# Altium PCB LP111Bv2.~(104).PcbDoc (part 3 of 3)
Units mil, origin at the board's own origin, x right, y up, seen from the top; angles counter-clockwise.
Board outline 3543.31 x 7480.32 mil, 4 copper layers (Top Layer, Signal Layer 1, Signal Layer 2, Bottom Layer), stack 40 mil thick; 284 components, 118 nets, 594 pads, 103 vias.
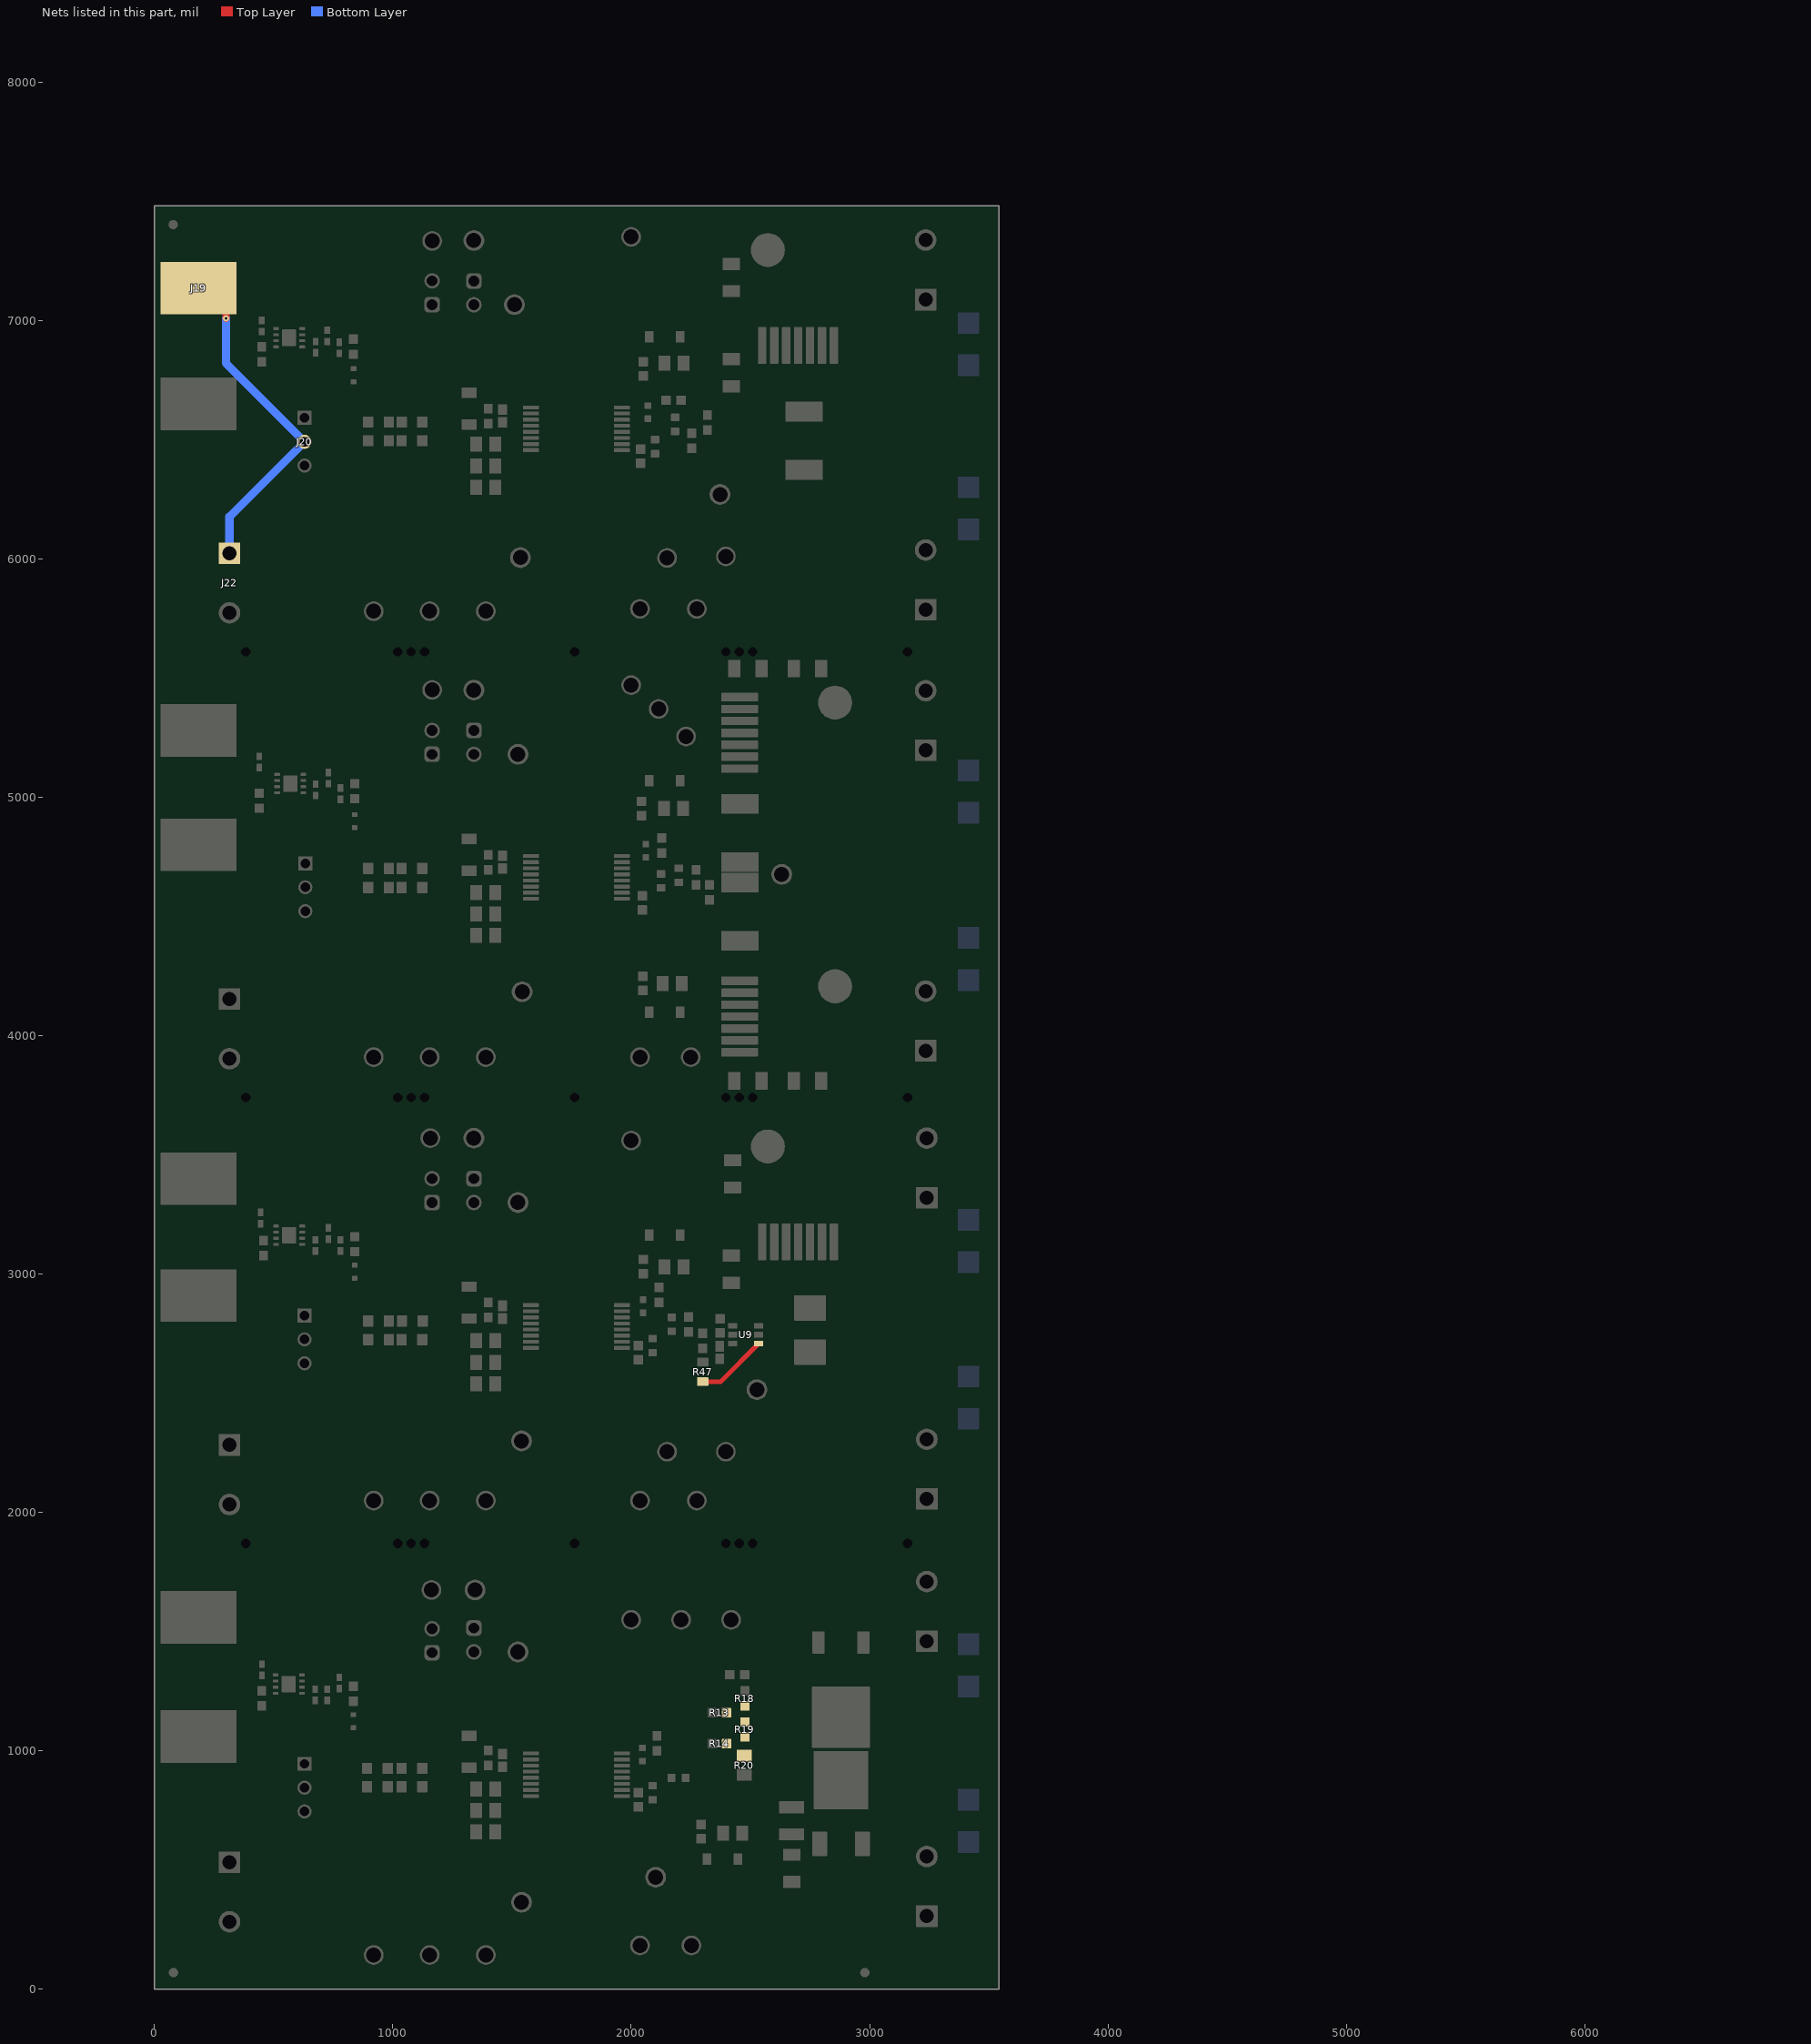
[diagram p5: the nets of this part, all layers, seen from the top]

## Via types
v1: diameter 24, hole 8, Top Layer to Bottom Layer, tented both sides, 77 vias
v2: diameter 19.68, hole 7.87, Top Layer to Bottom Layer, 16 vias
v3: diameter 27.56, hole 11.81, Top Layer to Bottom Layer, tented both sides, 10 vias

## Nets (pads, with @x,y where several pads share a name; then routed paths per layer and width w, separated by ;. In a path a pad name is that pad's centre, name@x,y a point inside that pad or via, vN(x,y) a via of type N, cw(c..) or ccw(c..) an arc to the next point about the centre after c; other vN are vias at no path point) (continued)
NetJ19_1: J19.1 J20.2 J22.1 | length 1436.1
  Top Layer w20: J19.1@185,7135.83 200,7135.83 J19.1@300,7035.83
  Top Layer w30: v3(300,7008.02) J19.1@300,7035.83
  Bottom Layer w35: v3(300,7008.02) 300,6820.86 J20.2@629.87,6490.99 314.96,6176.08 J22.1@314.96,6023.19
NetR13_2: R13.2 R18.1 R19.2
NetR14_2: R14.2 R19.1 R20.2
NetR47_2: R47.2 U9.1 | length 300.2
  Top Layer w20: R47.2@2299.93,2548.66 2374.8,2548.66 U9.1@2534.13,2707.99
pads on no net: FID1.1 FID2.1 FID3.1 H1.0 H2.0 H3.0 H4.0 H5.0 H6.0 H7.0 H8.0 H9.0 H10.0 H11.0 H12.0 H13.0 H14.0 H15.0 H16.0 SH-J1.0 SH-J2.0 SH-J3.0 SH-J4.0 SH-J5.0 SH-J6.0 SH-J7.0 SH-J8.0 SH-J9.0 SH-J10.0 SH-J11.0 SH-J12.0 U2.3 U2.7 U3.3 U3.7 U5.3 U5.7 U8.3 U8.7

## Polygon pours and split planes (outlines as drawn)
2VSSS on Top Layer "TOP_LAYER_2VSSS_P056" (solid, remove dead copper, pour order 56): 1930.14,4522.73 1930.14,4806.94 1982.34,4859.14 2249.94,4859.14 2291.63,4817.45 2291.63,4511.77 2250.63,4470.77 1982.1,4470.77
4VSSS on Top Layer "Top Layer-4VSSS" (solid, remove dead copper, pour order 52): 1930,115 2025,20 3062,20 3543.31,20 3543.31,475 3530,475 3530,662.5 2940,662.5 2940,565.32 2849.68,475 2247.51,475 2177.76,544.75 2177.76,691.48 2231,744.72 2369.48,744.72 2505.62,880.87 2504.34,882.14 2504.34,927.5 2275.27,1156.58 2000,1156.58 1928.23,1084.81 1928.23,744.72 1930,744.72
2VSSP on Top Layer "TOP_LAYER_2VSSP_P019" (solid, remove dead copper, pour order 19): 419.5,4935.31 548.27,4935.31 636.75,5023.78 860.61,5023.78 868.48,5031.65 868.48,5120.51 800.49,5188.5 419.5,5188.5
4VSSP on Top Layer "TOP_LAYER_4VSSP_P025" (solid, remove dead copper, pour order 25): 429.46,1160.97 543.34,1160.97 631.81,1249.45 855.67,1249.45 863.54,1257.32 863.54,1346.18 830.42,1379.31 429.46,1379.31
3VSSP on Top Layer "TOP_LAYER_3VSSP_P022" (solid, remove dead copper, pour order 22): 429.46,3040.98 543.34,3040.98 631.81,3129.45 855.67,3129.45 863.54,3137.32 863.54,3226.18 830.42,3259.31 429.46,3259.31
1VSSP on Top Layer "TOP_LAYER_1VSSP_P016" (solid, remove dead copper, pour order 16): 429.46,6806.25 543.34,6806.25 631.81,6894.72 855.67,6894.72 863.54,6902.6 863.54,6991.46 830.42,7024.58 429.46,7024.58
4VDDP_filtered on Top Layer "TOP_LAYER_4VDDP_FILTERED_P023" (solid, remove dead copper, pour order 23): 1100.36,872.07 1100.36,830.96 1290.36,640.96 1290.36,622.07 1373.09,622.07 1373.09,872.07 1411.81,910.79 1472.85,910.79 1472.85,955.33 1237.31,955.33 1154.05,872.07
NetD6_2 on Top Layer "TOP_LAYER_NETD6_2_P073" (solid, remove dead copper, pour order 73): 2807.87,1405 2669.45,1405 2499.45,1235 2454.79,1235 2454.79,1337.7 2622.08,1505 2807.87,1505
4HV+ on Top Layer "TOP_LAYER_4HV+_P072" (solid, remove dead copper, pour order 72): 2950,1405 2950,1780 3012.87,1842.87 3543.31,1842.87 3540,1839.57 3540,1405
3VSSS on Top Layer "TOP_LAYER_3VSSS_P071" (solid, remove dead copper, pour order 71): 3552.01,1900.22 3552.01,2439.59 3106.64,2439.59 2818.28,2727.95 2689.08,2727.95 2428.7,2467.57 1959.19,2467.57 1943.7,2452.08 1943.7,1929.91 1973.38,1900.22 3556.73,1900.22
3IN+ on Top Layer "TOP_LAYER_3IN+_P070" (solid, remove dead copper, pour order 70): 2582.47,3210 2582.47,2904.89 2680.94,2806.42 2821.15,2806.42 2867.61,2852.88 2867.61,3210
3VGATE on Top Layer "TOP_LAYER_3VGATE_P069" (solid, remove dead copper, pour order 69): 2195,3001.92 2250,3001.92 2303.08,3055 2563.58,3055 2563.58,3210 2460.43,3313.14 2460.43,3386.56 2361.81,3386.56 2180.25,3205 2180.25,3117.5 2195,3102.76 2195,3061.37
2HV- on Top Layer "TOP_LAYER_2HV-_P068" (solid, remove dead copper, pour order 68): 2780,4278.3 3467.64,4278.3 3545,4200.93 3543.31,4199.24 3543.31,3758.3 2787.87,3758.3 2775.67,3770.5 2775.67,4282.23
2FLT1_CMP on Top Layer "TOP_LAYER_2FLT1_CMP_P067" (solid, remove dead copper, pour order 67): 2598.31,4989.86 2598.31,5330 2538.3,5390 2373.49,5390 2312.4,5328.91 2312.4,4987.6 2370.28,4929.72 2538.17,4929.72
1VSSS on Top Layer "TOP_LAYER_1VSSS_P066" (solid, remove dead copper, pour order 66): 2188.86,6630.82 2166.47,6608.43 2166.47,6577.6 2335.33,6577.6 2341.39,6583.66 2333.66,6591.39 2333.66,6662.4 2310.13,6685.93 2188.86,6685.93
1VSSS on Top Layer "TOP_LAYER_1VSSS_P065" (solid, remove dead copper, pour order 65): 3543.31,5630.32 3543.31,6169.69 3051.97,6169.69 2806.65,6415 2637.34,6415 2420,6197.66 1950.49,6197.66 1935,6182.17 1935,5660 1964.68,5630.32 3548.03,5630.32
2HV+ on Top Layer "TOP_LAYER_2HV+_P064" (solid, remove dead copper, pour order 64): 2780,5067.64 3467.64,5067.64 3545,5145 3543.31,5146.69 3543.31,5587.64 2787.87,5587.64 2775.67,5575.43 2775.67,5063.7
3HV+ on Top Layer "TOP_LAYER_3HV+_P063" (solid, remove dead copper, pour order 63): 3548,3721.03 2498.39,3721.03 2498.39,3612.02 2387.09,3500.72 2389.26,3498.55 2389.26,3452.29 2913.12,3452.29 3056.66,3308.75 3056.66,3180.72 3548,3180.72
1HV+ on Top Layer "TOP_LAYER_1HV+_P062" (solid, remove dead copper, pour order 62): 3543.31,7480.32 2493.7,7480.32 2493.7,7371.3 2382.4,7260 2384.57,7257.84 2384.57,7211.57 2908.43,7211.57 3051.97,7068.03 3051.97,6940 3543.31,6940
1ALM1_CMP on Top Layer "TOP_LAYER_1ALM1_CMP_P061" (solid, remove dead copper, pour order 61): 2585,6970 2585,6639.25 2646.65,6577.6 2807.6,6577.6 2870,6640 2870,6970
1VGATE on Top Layer "TOP_LAYER_1VGATE_P060" (solid, remove dead copper, pour order 60): 2180,6894.8 2197.72,6877.09 2197.72,6766.26 2333.66,6766.26 2382.4,6815 2565,6815 2565,6970 2495.43,6970 2455.43,7010 2455.43,7147.44 2352.44,7147.44 2180,6975
4VGATE on Top Layer "TOP_LAYER_4VGATE_P059" (solid, remove dead copper, pour order 59): 2421.9,505 2609.35,505 2637.49,533.14 2795.74,533.14 2820,557.4 2820,661.15 2737.11,661.15 2726.07,672.19 2514.57,672.19 2499.45,687.31 2443.08,687.31 2425,669.23 2425,587.59 2421.9,584.5
NetC17_1 on Top Layer "TOP_LAYER_NETC17_1_P043" (solid, remove dead copper, pour order 43): 2619.77,740 2973.05,740 3000.01,766.95 3000.01,853.52 2774.47,853.52 2712.48,791.54 2620.32,791.54
NetR14_2 on Top Layer "TOP_LAYER_NETR14_2_P041" (solid, remove dead copper, pour order 41): 2406.93,1075.62 2379.4,1048.1 2380.44,1047.06 2380.44,1008.18 2434.12,954.5 2505.62,954.5 2505.62,1059.42 2489.42,1075.62
NetR13_2 on Top Layer "TOP_LAYER_NETR13_2_P040" (solid, remove dead copper, pour order 40): 2409.58,1207.5 2382.06,1179.98 2383.1,1178.94 2383.1,1140.06 2416.48,1106.68 2493.1,1106.68 2493.1,1206.48 2492.07,1207.5
2FLT2_CMP on Top Layer "TOP_LAYER_2FLT2_CMP_P033" (solid, remove dead copper, pour order 33): 2631.26,3997.94 2631.26,4347.32 2540.45,4438.13 2372.2,4438.13 2283.93,4349.86 2283.93,3996.07 2370,3910 2543.32,3910
2VGATE1 on Top Layer "TOP_LAYER_2VGATE1_P031" (solid, remove dead copper, pour order 31): 2525.31,3845.68 2525.31,3774.81 2707.04,3774.81 2705.07,3776.78 2705.07,3845.68
2VGATE2 on Top Layer "TOP_LAYER_2VGATE2_P030" (solid, remove dead copper, pour order 30): 2521.11,5575.43 2521.11,5504.57 2702.83,5504.57 2700.87,5506.54 2700.87,5575.43
2VSSS on Top Layer "TOP_LAYER_2VSSS_P026" (solid, remove dead copper, pour order 26): 2372.36,4591.97 2629.69,4591.97 2673.07,4635.35 2673.07,4720.08 2623.89,4769.25 2372.36,4769.25
4LDO_OUT on Top Layer "TOP_LAYER_4LDO_OUT_P024" (solid, remove dead copper, pour order 24): 609.86,1249.45 639.67,1249.45 654.4,1234.72 759.52,1234.72 763,1231.24 850,1231.24 850,1189.22 639.87,1189.22 609.86,1219.23
3LDO_OUT on Top Layer "TOP_LAYER_3LDO_OUT_P021" (solid, remove dead copper, pour order 21): 609.86,3129.45 639.67,3129.45 654.4,3114.73 759.52,3114.73 763,3111.24 850,3111.24 850,3069.22 639.87,3069.22 609.86,3099.23
3VDDP_filtered on Top Layer "TOP_LAYER_3VDDP_FILTERED_P020" (solid, remove dead copper, pour order 20): 1100.36,2752.07 1100.36,2710.96 1290.36,2520.96 1290.36,2502.07 1373.09,2502.07 1373.09,2752.07 1411.81,2790.79 1482.24,2790.79 1482.24,2825.94 1472.85,2835.33 1237.31,2835.33 1154.05,2752.07
2LDO_OUT on Top Layer "TOP_LAYER_2LDO_OUT_P018" (solid, remove dead copper, pour order 18): 614.79,5023.78 644.61,5023.78 659.33,5009.06 764.45,5009.06 767.94,5005.57 854.93,5005.57 854.93,4963.55 644.81,4963.55 614.79,4993.56
1LDO_OUT on Top Layer "TOP_LAYER_1LDO_OUT_P015" (solid, remove dead copper, pour order 15): 609.86,6894.72 639.67,6894.72 654.4,6880 759.52,6880 763,6876.52 850,6876.52 850,6834.49 639.87,6834.49 609.86,6864.51
1ALM1_CMP on Top Layer "TOP_LAYER_1ALM1_CMP_P014" (solid, remove dead copper, pour order 14): 2646.65,6633.6 2646.65,6577.6 2642.94,6577.6 2515,6705.55 2396.54,6705.55 2396.54,6740 2545,6740
NetC17_1 on Top Layer "TOP_LAYER_NETC17_1_P005" (solid, remove dead copper, pour order 5): 2756.49,755 2756.49,1270 3000.01,1270 3000.01,755
1VDDP_filtered on Top Layer "TOP_LAYER_1VDDP_FILTERED_P001" (solid, remove dead copper, pour order 1): 1100.36,6517.35 1100.36,6476.24 1290.36,6286.24 1290.36,6267.35 1373.09,6267.35 1373.09,6517.35 1411.81,6556.07 1482.24,6556.07 1482.24,6591.22 1472.85,6600.61 1237.31,6600.61 1154.05,6517.35
2VDDP_filtered on Top Layer "TOP_LAYER_2VDDP_FILTERED_P000" (solid, remove dead copper, pour order 0): 1100,4644.73 1100,4598.89 1290,4408.89 1290,4390 1372.73,4390 1372.73,4640 1411.46,4678.72 1481.88,4678.72 1481.88,4713.87 1472.49,4723.26 1236.95,4723.26 1158.42,4644.73
1VSSS on Bottom Layer "BOTTOM_LAYER_1VSSS_P104" (solid, remove dead copper, pour order 104): 3543.31,5630.32 3543.31,6169.69 3051.97,6169.69 2806.65,6415 2637.34,6415 2420,6197.66 1950.49,6197.66 1935,6182.17 1935,5660 1964.68,5630.32 3548.03,5630.32
3VSSS on Bottom Layer "BOTTOM_LAYER_3VSSS_P086" (solid, remove dead copper, pour order 86): 3552.01,1900.22 3552.01,2439.59 3106.64,2439.59 2818.28,2727.95 2689.08,2727.95 2428.7,2467.57 1959.19,2467.57 1943.7,2452.08 1943.7,1929.91 1973.38,1900.22 3556.73,1900.22
2VSSS on Bottom Layer "BOTTOM_LAYER_2VSSS_P055" (solid, remove dead copper, pour order 55): 1930.91,4521.96 1930.91,4806.16 1983.11,4858.37 2250.71,4858.37 2292.4,4816.68 2292.4,4511 2251.4,4470 1982.87,4470
4VSSS on Bottom Layer "Bottom Layer-4VSSS" (solid, remove dead copper, pour order 51): 1930,115 2025,20 3062,20 3543.31,20 3543.31,475 3530,475 3530,662.5 2940,662.5 2940,565.32 2849.68,475 2247.51,475 2177.76,544.75 2177.76,691.48 2231,744.72 2369.48,744.72 2505.62,880.87 2504.34,882.14 2504.34,927.5 2275.27,1156.58 2000,1156.58 1928.23,1084.81 1928.23,744.72 1930,744.72
1HV+ on Bottom Layer "BOTTOM_LAYER_1HV+_P077" (solid, remove dead copper, pour order 77): 3543.31,7480.32 2493.7,7480.32 2493.7,7371.3 2382.4,7260 2384.57,7257.84 2384.57,7211.57 2908.43,7211.57 3051.97,7068.03 3051.97,6940 3543.31,6940
4HV+ on Bottom Layer "BOTTOM_LAYER_4HV+_P087" (solid, remove dead copper, pour order 87): 2950,1405 2950,1780 3012.87,1842.87 3543.31,1842.87 3540,1839.57 3540,1405
2HV- on Bottom Layer "BOTTOM_LAYER_2HV-_P083" (solid, remove dead copper, pour order 83): 2780,4278.3 3467.64,4278.3 3545,4200.93 3543.31,4199.24 3543.31,3758.3 2787.87,3758.3 2775.67,3770.5 2775.67,4282.23
2FLT1_CMP on Bottom Layer "BOTTOM_LAYER_2FLT1_CMP_P082" (solid, remove dead copper, pour order 82): 2598.31,4989.86 2598.31,5330 2538.3,5390 2373.49,5390 2312.4,5328.91 2312.4,4987.6 2370.28,4929.72 2538.17,4929.72
1VSSS on Bottom Layer "BOTTOM_LAYER_1VSSS_P081" (solid, remove dead copper, pour order 81): 2188.86,6630.82 2166.47,6608.43 2166.47,6577.6 2335.33,6577.6 2341.39,6583.66 2333.66,6591.39 2333.66,6662.4 2310.13,6685.93 2188.86,6685.93
2HV+ on Bottom Layer "BOTTOM_LAYER_2HV+_P079" (solid, remove dead copper, pour order 79): 2780,5067.64 3467.64,5067.64 3545,5145 3543.31,5146.69 3543.31,5587.64 2787.87,5587.64 2775.67,5575.43 2775.67,5063.7
3HV+ on Bottom Layer "BOTTOM_LAYER_3HV+_P078" (solid, remove dead copper, pour order 78): 3548,3721.03 2498.39,3721.03 2498.39,3612.02 2387.09,3500.72 2389.26,3498.55 2389.26,3452.29 2913.12,3452.29 3056.66,3308.75 3056.66,3180.72 3548,3180.72
2FLT2_CMP on Bottom Layer "BOTTOM_LAYER_2FLT2_CMP_P028" (solid, remove dead copper, pour order 28): 2631.26,3997.94 2631.26,4347.32 2540.45,4438.13 2372.2,4438.13 2283.93,4349.86 2283.93,3996.07 2370,3910 2543.32,3910
4VSSS on Signal Layer 1 "Signal Layer 1-4VSSS" (solid, remove dead copper, pour order 53): 1930,115 2025,20 3062,20 3543.31,20 3543.31,475 3530,475 3530,662.5 2940,662.5 2940,565.32 2849.68,475 2247.51,475 2177.76,544.75 2177.76,691.48 2231,744.72 2369.48,744.72 2505.62,880.87 2504.34,882.14 2504.34,927.5 2275.27,1156.58 2000,1156.58 1928.23,1084.81 1928.23,744.72 1930,744.72
4HV+ on Signal Layer 1 "SIGNAL_LAYER_1_4HV+_P102" (solid, remove dead copper, pour order 102): 2950,1405 2950,1780 3012.87,1842.87 3543.31,1842.87 3540,1839.57 3540,1405
3VSSS on Signal Layer 1 "SIGNAL_LAYER_1_3VSSS_P101" (solid, remove dead copper, pour order 101): 3552.01,1900.22 3552.01,2439.59 3106.64,2439.59 2818.28,2727.95 2689.08,2727.95 2428.7,2467.57 1959.19,2467.57 1943.7,2452.08 1943.7,1929.91 1973.38,1900.22 3556.73,1900.22
2HV- on Signal Layer 1 "SIGNAL_LAYER_1_2HV-_P098" (solid, remove dead copper, pour order 98): 2780,4278.3 3467.64,4278.3 3545,4200.93 3543.31,4199.24 3543.31,3758.3 2787.87,3758.3 2775.67,3770.5 2775.67,4282.23
2FLT1_CMP on Signal Layer 1 "SIGNAL_LAYER_1_2FLT1_CMP_P097" (solid, remove dead copper, pour order 97): 2598.31,4989.86 2598.31,5330 2538.3,5390 2373.49,5390 2312.4,5328.91 2312.4,4987.6 2370.28,4929.72 2538.17,4929.72
1VSSS on Signal Layer 1 "SIGNAL_LAYER_1_1VSSS_P095" (solid, remove dead copper, pour order 95): 3543.31,5630.32 3543.31,6169.69 3051.97,6169.69 2806.65,6415 2637.34,6415 2420,6197.66 1950.49,6197.66 1935,6182.17 1935,5660 1964.68,5630.32 3548.03,5630.32
2HV+ on Signal Layer 1 "SIGNAL_LAYER_1_2HV+_P094" (solid, remove dead copper, pour order 94): 2780,5067.64 3467.64,5067.64 3545,5145 3543.31,5146.69 3543.31,5587.64 2787.87,5587.64 2775.67,5575.43 2775.67,5063.7
3HV+ on Signal Layer 1 "SIGNAL_LAYER_1_3HV+_P093" (solid, remove dead copper, pour order 93): 3548,3721.03 2498.39,3721.03 2498.39,3612.02 2387.09,3500.72 2389.26,3498.55 2389.26,3452.29 2913.12,3452.29 3056.66,3308.75 3056.66,3180.72 3548,3180.72
1HV+ on Signal Layer 1 "SIGNAL_LAYER_1_1HV+_P092" (solid, remove dead copper, pour order 92): 3543.31,7480.32 2493.7,7480.32 2493.7,7371.3 2382.4,7260 2384.57,7257.84 2384.57,7211.57 2908.43,7211.57 3051.97,7068.03 3051.97,6940 3543.31,6940
2VSSS on Signal Layer 1 "SIGNAL_LAYER_1_2VSSS_P057" (solid, remove dead copper, pour order 57): 1930.91,4521.96 1930.91,4806.16 1983.11,4858.37 2250.71,4858.37 2292.4,4816.68 2292.4,4511 2251.4,4470 1982.87,4470
3VSSS on Signal Layer 1 "SIGNAL_LAYER_1_3VSSS_P046" (solid, remove dead copper, pour order 46): 1930.91,2680 1995.91,2615 2382.26,2615 2467.64,2700.38 2467.64,2827.66 2333.37,2961.93 1996.94,2961.93 1930.91,2895.9
2FLT2_CMP on Signal Layer 1 "SIGNAL_LAYER_1_2FLT2_CMP_P032" (solid, remove dead copper, pour order 32): 2631.26,3997.94 2631.26,4347.32 2540.45,4438.13 2372.2,4438.13 2283.93,4349.86 2283.93,3996.07 2370,3910 2543.32,3910
4HV+ on Signal Layer 2 "SIGNAL_LAYER_2_4HV+_P038" (solid, remove dead copper, pour order 38): 2950,1405 2950,1780 3012.87,1842.87 3543.31,1842.87 3540,1839.57 3540,1405
1VSSS on Signal Layer 2 "SIGNAL_LAYER_2_1VSSS_P013" (solid, remove dead copper, pour order 13): 2188.86,6630.82 2166.47,6608.43 2166.47,6577.6 2335.33,6577.6 2341.39,6583.66 2333.66,6591.39 2333.66,6662.4 2310.13,6685.93 2188.86,6685.93
1HV+ on Signal Layer 2 "SIGNAL_LAYER_2_1HV+_P009" (solid, remove dead copper, pour order 9): 3543.31,7480.32 2493.7,7480.32 2493.7,7371.3 2382.4,7260 2384.57,7257.84 2384.57,7211.57 2908.43,7211.57 3051.97,7068.03 3051.97,6940 3543.31,6940
1VSSS on Signal Layer 2 "SIGNAL_LAYER_2_1VSSS_P012" (solid, remove dead copper, pour order 12): 3543.31,5630.32 3543.31,6169.69 3051.97,6169.69 2806.65,6415 2637.34,6415 2420,6197.66 1950.49,6197.66 1935,6182.17 1935,5660 1964.68,5630.32 3548.03,5630.32
2HV+ on Signal Layer 2 "SIGNAL_LAYER_2_2HV+_P011" (solid, remove dead copper, pour order 11): 2780,5067.64 3467.64,5067.64 3545,5145 3543.31,5146.69 3543.31,5587.64 2787.87,5587.64 2775.67,5575.43 2775.67,5063.7
2FLT1_CMP on Signal Layer 2 "SIGNAL_LAYER_2_2FLT1_CMP_P027" (solid, remove dead copper, pour order 27): 2598.31,4989.86 2598.31,5330 2538.3,5390 2373.49,5390 2312.4,5328.91 2312.4,4987.6 2370.28,4929.72 2538.17,4929.72
2HV- on Signal Layer 2 "SIGNAL_LAYER_2_2HV-_P029" (solid, remove dead copper, pour order 29): 2780,4278.3 3467.64,4278.3 3545,4200.93 3543.31,4199.24 3543.31,3758.3 2787.87,3758.3 2775.67,3770.5 2775.67,4282.23
3HV+ on Signal Layer 2 "SIGNAL_LAYER_2_3HV+_P010" (solid, remove dead copper, pour order 10): 3548,3721.03 2498.39,3721.03 2498.39,3612.02 2387.09,3500.72 2389.26,3498.55 2389.26,3452.29 2913.12,3452.29 3056.66,3308.75 3056.66,3180.72 3548,3180.72
3VSSS on Signal Layer 2 "SIGNAL_LAYER_2_3VSSS_P037" (solid, remove dead copper, pour order 37): 3552.01,1900.22 3552.01,2439.59 3106.64,2439.59 2818.28,2727.95 2689.08,2727.95 2428.7,2467.57 1959.19,2467.57 1943.7,2452.08 1943.7,1929.91 1973.38,1900.22 3556.73,1900.22
2VSSS on Signal Layer 2 "SIGNAL_LAYER_2_2VSSS_P058" (solid, remove dead copper, pour order 58): 1930.91,4521.96 1930.91,4806.16 1983.11,4858.37 2250.71,4858.37 2292.4,4816.68 2292.4,4511 2251.4,4470 1982.87,4470
4VSSS on Signal Layer 2 "Signal Layer 2-4VSSS" (solid, remove dead copper, pour order 54): 1930,115 2025,20 3062,20 3543.31,20 3543.31,475 3530,475 3530,662.5 2940,662.5 2940,565.32 2849.68,475 2247.51,475 2177.76,544.75 2177.76,691.48 2231,744.72 2369.48,744.72 2505.62,880.87 2504.34,882.14 2504.34,927.5 2275.27,1156.58 2000,1156.58 1928.23,1084.81 1928.23,744.72 1930,744.72
2FLT2_CMP on Signal Layer 2 "SIGNAL_LAYER_2_2FLT2_CMP_P034" (solid, remove dead copper, pour order 34): 2631.26,3997.94 2631.26,4347.32 2540.45,4438.13 2372.2,4438.13 2283.93,4349.86 2283.93,3996.07 2370,3910 2543.32,3910

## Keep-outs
Keep-Out Layer:
  text ".Layer_Name" at 577,-858.49 h60

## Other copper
Top Layer:
  pour cut-out: 2631.26,3210 2631.26,2929.69 2682.09,2878.86 2682.09,2856.05 2615.19,2922.95 2615.19,3210
  pour cut-out: 2630,6975 2630,6669.59 2646.65,6652.94 2646.65,6633.6 2615.82,6664.42 2615.82,6975
  text ".Layer_Name" at 577,-858.49 h60
Bottom Layer:
  text ".Layer_Name" at 577,-858.49 h60

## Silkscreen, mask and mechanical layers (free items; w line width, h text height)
Top Overlay:
  drawing of 177 lines, arcs and shapes, not listed
  text "CE" at 1142.67,7426.09 h30
  text "EN" at 1312.68,7426.09 h30
  text "VDRV" at 1941.69,7426.09 h30
  text "Uni-OCP no CSA" at 420,7400.74 h100
  text "CE" at 1051,7146 h30
  text "EN" at 1231,7146 h30
  text "+" at 355,7111.08 h90
  text "VDDP" at 1288.6,6904.37 h30
  text "HV+" at 3240,6852.54 h90
  text "-" at 365,6629.34 h90
  text "LDO" at 720.18,6581.25 h30
  text "+" at 514.59,6474.78 h30
  text "Device" at 714.37,6375.16 h30
  text "TPSI3100-Q1" at 1626.39,6364.5 h30
  text "VSSS" at 2473.64,6251 h30
  text "VSSS" at 3228,6203.23 h90
  text "VDDH" at 2093.93,6096 h30
  text "VDDM" at 2343.53,6096 h30
  text "+" at 510,6006.08 h90
  text "VSSP" at 1486,5886 h30
  text "Max DC Load: / 750-V / 5-A" at 2565,5775 h40
  text "-" at 520,5754.34 h90
  text "PGOOD" at 851,5658.84 h30
  text "nFLT" at 1092.89,5658.84 h30
  text "nALM" at 1333.54,5658.84 h30
  text "FLT-CMP" at 1941,5658.84 h30
  text "ALM-CMP" at 2176.53,5658.84 h30
  text "VDRV" at 1944.66,5551.09 h30
  text "CE" at 1144.02,5542.72 h30
  text "EN" at 1314.02,5542.72 h30
  text "Bi-OCP no CSA" at 445.58,5514.65 h100
  text "VDDH" at 2169.44,5428.6 h30 r45
  text "VDDM" at 2271.56,5324.77 h30 r45
  text "+" at 355,5256.08 h90
  text "VDDP" at 1288.6,5029.63 h30
  text "HV1+" at 3221.3,4966.15 h90
  text "-" at 365,4774.34 h90
  text "Max DC Load: / 750-Vdc / 5-A" at 2710,4755 h40
  text "LDO" at 725.18,4712.32 h30
  text "VSSS" at 2726,4662.96 h30
  text "+" at 519.59,4605.85 h30
  text "Device" at 719.37,4506.23 h30
  text "TPSI3110-Q1" at 1620.82,4484.5 h30
  text "HV2+" at 3221.3,4352.04 h90
  text "+" at 510,4135.14 h90
  text ".PRJ_Title" at 599.69,4135.14 h108.27
  text "VSSP" at 1485.52,4058.76 h30
  text "-" at 520,3883.39 h90
  text "PGOOD" at 850.16,3795.8 h30
  text "nFLT1" at 1092.05,3795.8 h30
  text "nFLT2" at 1332.71,3795.8 h30
  text "FLT2-CMP" at 1876,3791 h30
  text "FLT1-CMP" at 2139.45,3791 h30
  text "CE" at 1140.73,3657.72 h30
  text "EN" at 1310.73,3657.72 h30
  text "VDRV" at 1936.91,3652.62 h30
  text "Uni-OCP with CSA" at 389.24,3644.65 h100
  text "+" at 355,3376.08 h90
  text "VDDP" at 1288.6,3149.63 h30
  text "HV+" at 3260,3085.25 h90
  text "-" at 365,2884.34 h90
  text "LDO" at 724.37,2815.98 h30
  text "+" at 518.78,2709.51 h30
  text "Device" at 718.56,2609.89 h30
  text "TPSI3100-Q1" at 1625.51,2600 h30
  text "VSSS" at 2628.12,2497.72 h30
  text "VSSS" at 3250.37,2473.23 h90
  text "VDDH" at 2090.12,2340.32 h30
  text "VDDM" at 2339.72,2340.32 h30
  text "'.PRJ_Number'.PCB_Rev" at 1076.04,2257.92 h108.27
  text "+" at 508.16,2252.89 h90
  text "VSSP" at 1483.63,2171.8 h30
  text "-" at 518.16,2001.15 h90
  text "Max DC Load: / 750-V / 5-A" at 2565,1994.41 h40
  text "PGOOD" at 850.93,1933.45 h30
  text "nFLT" at 1092.82,1933.45 h30
  text "nALM" at 1333.47,1933.45 h30
  text "ALM-CMP" at 1938.26,1930.86 h30
  text "FLT-CMP" at 2173.79,1930.86 h30
  text "DESAT" at 577.76,1774.65 h100
  text "CE" at 1147.5,1767.72 h30
  text "EN" at 1317.5,1767.72 h30
  text "VDDH" at 2149.57,1645.33 h30
  text "VDDM" at 2359.62,1645.33 h30
  text "VDRV" at 1934.23,1641.85 h30
  text "+" at 355,1536.08 h90
  text "VDDP" at 1288.6,1251.35 h30
  text "HV+" at 3245,1225.25 h90
  text "-" at 367.13,1036.37 h90
  text "LDO" at 731.32,935.98 h30
  text "+" at 525.73,829.51 h30
  text "Device" at 725.51,729.89 h30
  text "VSSS" at 3235.33,723.23 h90
  text "TPSI3133-Q1" at 1620.82,720 h30
  text "VSSS" at 2039.55,559.87 h30
  text "+" at 512.13,516.08 h90
  text "-" at 522.13,264.34 h90
  text "VSSP" at 1485.63,249.36 h30
  text "Max DC Load: / 600-V / 5-A" at 2565,78.68 h40
  text "ALM-CMP" at 1930.01,71.6 h30
  text "FLT-CMP" at 2165.55,71.6 h30
  text "PGOOD" at 860.05,23.15 h30
  text "nFLT" at 1101.94,23.15 h30
  text "nALM" at 1342.59,23.15 h30
  text ".Layer_Name" at 577,-858.49 h60
Bottom Overlay:
  text ".Layer_Name" at 577,-858.49 h60
Top Paste:
  text ".Layer_Name" at 577,-858.49 h60
Bottom Paste:
  text ".Layer_Name" at 577,-858.49 h60
Top Solder:
  text ".Layer_Name" at 577,-858.49 h60
  text ".Layer_Name" at 577,-858.49 h60
Bottom Solder:
  text ".Layer_Name" at 577,-858.49 h60
Drill Guide:
  text ".Layer_Name" at 577,-858.49 h60
M1 Board Outline:
  the board outline again, w10
  text ".Layer_Name" at 577,-858.49 h60
M2 Board Dimensions:
  rectangle: 0,-275 125,-150
  rectangle: 125,-400 500,-275
  lines w7: 0,-275 1000,-275 ; 125,-400 125,-150 ; 250,-400 250,-150 ; 500,-400 500,-150 ; 750,-400 750,-150 ; 0,-400 1000,-400 1000,-150 0,-150 0,-400
  text ".Layer_Name" at 577,-858.49 h60
M3 3D STEP Top:
  text ".Layer_Name" at 577,-858.49 h60
M4 3D STEP Bottom:
  text ".Layer_Name" at 577,-858.49 h60
M5 Assembly Top:
  lines w10: -292,-930.17 6308,-930.17 ; -292,-726.83 6310,-726.83 ; -292,-523.5 -292,-1133.5 3713,-1133.5 6310,-1133.5 6310,-523.5 -291.5,-523.5 -291.5,-1133.5 1284,-1133.5 ; 2173,-1133.5 2173,-523.5 ; 3440,-726.83 3440,-523.5 ; 4280,-726.83 4280,-523.5 ; 4902,-1140 4902,-937.17
  text "COMPONENTS MARKED 'DNP' SHOULD NOT BE POPULATED." at 1153.5,-318.5 h60
  text "ASSEMBLY VARIANT:" at 1153,-434 h60
  text ".VariantName" at 2189,-434 h60
  text "PCB VIEWED FROM TOP SIDE" at -228.5,-655.67 h60
  text "BOARD #:" at 2248,-655.67 h60
  text ".PRJ_Number" at 2793.5,-655.67 h60
  text "REV:" at 3638,-655.67 h60
  text ".PCB_Rev" at 3929.5,-655.67 h60
  text "SVN REV:" at 4476,-655.67 h60
  text ".VersionControl_RevNumber" at 4982,-655.67 h60
  text "TID #:" at 2248,-859 h60
  text ".TID" at 2793.5,-859 h60
  text "PLOT NAME =" at -228.5,-1064.34 h60
  text ".plot_File_Name" at 577,-1064.34 h60
  text "GENERATED    :" at 2250,-1064.34 h60
  text ".Print_Date" at 3119.5,-1064.34 h60
  text ".Print_Time" at 3848.5,-1064.34 h60
  text "TEXAS INSTRUMENTS" at 5113,-1064.34 h60
M6 Assembly Bottom:
  lines w10: -292.5,-727.33 6309.5,-727.33 ; -290.5,-930.67 6309.5,-930.67 ; 1115.5,-1140.5 1115.5,-937.67 ; 1737.5,-727.33 1737.5,-524 ; 2577.5,-727.33 2577.5,-524 ; 3844.5,-1134 3844.5,-524 ; 4733.5,-1134 6309,-1134 6309,-524 -292.5,-524 -292.5,-1134 2304.5,-1134 6309.5,-1134 6309.5,-524
  text "COMPONENTS MARKED 'DNP' SHOULD NOT BE POPULATED." at 6102,-318 h60
  text ".VariantName" at 5058,-434 h60
  text "ASSEMBLY VARIANT:" at 6097,-434 h60
  text ".VersionControl_RevNumber" at 1035.5,-656.17 h60
  text "SVN REV:" at 1541.5,-656.17 h60
  text ".PCB_Rev" at 2088,-656.17 h60
  text "REV:" at 2379.5,-656.17 h60
  text ".PRJ_Number" at 3224,-656.17 h60
  text "BOARD #:" at 3769.5,-656.17 h60
  text "PCB VIEWED FROM BOTTOM SIDE" at 6246,-656.17 h60
  text ".TID" at 3224,-859.5 h60
  text "TID #:" at 3769.5,-859.5 h60
  text "TEXAS INSTRUMENTS" at 904.5,-1064.84 h60
  text ".Print_Time" at 2169,-1064.84 h60
  text ".Print_Date" at 2898,-1064.84 h60
  text "GENERATED    :" at 3767.5,-1064.84 h60
  text ".plot_File_Name" at 5440.5,-1064.84 h60
  text "PLOT NAME =" at 6246,-1064.84 h60
M9 Title Sheet:
  drawing of 57 lines, arcs and shapes, not listed
  text "1" at 739.84,8036.5 h70
  text "2" at 3235.5,8036.5 h70
  text "3" at 5724.84,8036.5 h70
  text "4" at 8231.51,8036.5 h70
  text "5" at 10730.5,8036.5 h70
  text "6" at 13235.5,8036.5 h70
  text "A" at -416.5,6893.5 h70
  text "A" at 14383.5,6893.5 h70
  text "B" at -416.5,4513.5 h70
  text "B" at 14383.5,4513.5 h70
  text "C" at -416.5,2138.5 h70
  text "C" at 14383.5,2138.5 h70
  text "PROJECT TITLE:" at 11343.5,277.5 h45
  text ".PRJ_Title" at 11393.5,144.17 h70
  text "DESIGNED FOR:" at 11343.5,-23.5 h45
  text ".PRJ_Customer" at 11393.5,-163.5 h70
  text "D" at -416.5,-231.5 h70
  text "D" at 14383.5,-231.5 h70
  text "FILE NAME:" at 11343.5,-323.5 h45
  text ".PCB_File_Name_No_Path" at 11393.5,-443.5 h70
  text "Texas Instruments (TI) and/or its licensors do not warrant the accuracy or completeness of this specification" at 6374,-605.34 h45
  text "ENGINEER:" at 11343.5,-613.5 h45
  text "LAYOUT BY:" at 12848.5,-613.5 h45
  text "or any information contained therein. TI and/or its licensors do not warrant that this design will meet" at 6329.01,-718 h45
  text ".PRJ_Engineer" at 11393.5,-768.49 h70
  text ".PCB_Layout" at 12899,-768.49 h70
  text "the specifications, will be suitable for your application or fit for any particular purpose, or will operate in" at 6329.01,-830.67 h45
  text ".Layer_Name" at 577,-858.49 h60
  text "ALTIUM DESIGNER VERSION:" at 12848.5,-923.5 h45
  text "an implementation. TI and/or its licensors do not warrant that the design is production worthy. You should" at 6329.01,-943.33 h45
  text "completely validate and test your design implementation to confirm the system functionality for your application." at 6374,-1056 h45
  text ".print_Scale" at 11393.5,-1056.83 h70
  text ".Application_BuildNumber" at 12899,-1056.83 h70
  text "1" at 739.84,-1263.5 h70
  text "2" at 3235.5,-1263.5 h70
  text "3" at 5724.84,-1263.5 h70
  text "4" at 8231.51,-1263.5 h70
  text "5" at 10730.5,-1263.5 h70
  text "6" at 13235.5,-1263.5 h70
M10 Fab Notes:
  drawing of 189 lines, arcs and shapes, not listed
  text "DESIGN INFORMATION" at 12382.02,6356.17 h60
  text "MIN. TRACK WIDTH:" at 11737.46,6224.05 h60
  text "8" at 12833.7,6224.05 h60
  text "MIL" at 12988.46,6224.05 h60
  text "7.874" at 12667.32,6102.36 h60
  text "MIN. CLEARANCE:" at 11737.46,6099.92 h60
  text "MIL" at 12988.46,6099.92 h60
  text "MIN. VIA PAD SIZE:" at 11737.46,5975.8 h60
  text "24" at 12803.71,5975.8 h60
  text "MIL" at 12988.46,5975.8 h60
  text "0.05mm (2MIL)" at 12432.46,5845.9 h60
  text "MINIMUM ANNULAR RING" at 11408.23,5837.67 h60
  text "EXTERNAL" at 13140.46,5837.67 h60
  text "PER" at 11608.23,5727.55 h60
  text "IPC-D-275 CLASS 2 LEVEL C" at 11828.23,5727.54 h60
  text "MIL, HOLES" at 13316.46,5627.07 h60
  text "+/-" at 12924,5618.48 h60
  text "+/-" at 13778,5618.48 h60
  text "REGISTRATION TOLERANCES:" at 11408.23,5617.42 h60
  text "METAL" at 12608,5617.42 h60
  text "5" at 13184.2,5617.42 h60
  text "3" at 14017.2,5617.42 h60
  text "MIL" at 14133.46,5617.42 h60
  text "HOLE SIZE TOLERANCE (UNLESS OTHERWISE SPECIFIED):" at 11408.23,5519.1 h60
  text "+/-" at 13778,5516.23 h60
  text "3" at 14017.2,5515.17 h60
  text "MIL" at 14133.46,5515.17 h60
  text "MATERIAL:" at 11333.46,5377.52 h60
  text "FR-4 High Tg" at 12319.9,5249 h60
  text "X" at 12175.46,5241.01 h60
  text "FR-4" at 11754.46,5236.49 h60
  text "OTHER" at 13242.46,5236.49 h60
  text "62 MIL (1.6mm) +/-10%" at 12074.56,5093.46 h60
  text "X" at 11954.46,5091.01 h60
  text "THICKNESS:" at 11408.23,5085.24 h60
  text "OTHER" at 13359.46,5085.24 h60
  text "TOLERANCE:" at 11408.23,4946.92 h60
  text "X" at 12256.46,4946.92 h60
  text "ANSI IPC-6012 TYPE 3 CLASS 2" at 12434.48,4946.92 h60
  text "OTHER +/-" at 12434.46,4802.73 h60
  text "BOW & TWIST:" at 11408.23,4657.54 h60
  text "X" at 12256.46,4657.54 h60
  text "ANSI IPC-6012 TYPE 3 CLASS 2" at 12434.48,4657.54 h60
  text "OTHER +/-" at 12434.46,4510.85 h60
  text "DRILLING:" at 11333.46,4380.23 h60
  text "NC_DRILL FILES" at 13094.46,4275.04 h60
  text "REFERENCE:" at 11408.23,4271.1 h60
  text "X" at 12065.46,4271.01 h60
  text "AS SHOWN" at 12243.46,4271.1 h60
  text "X" at 12966.46,4271.1 h60
  text "OTHER" at 13392.46,4128.85 h60
  text "PTH COPPER THICKNESS:" at 11407.91,4125.32 h60
  text "X" at 12547.14,4125.32 h60
  text "20-30 um" at 12675.14,4125.32 h60
  text "BOARD FINISH:" at 11333.46,3977.73 h60
  text "SILKSCREEN:" at 11488.68,3867.6 h60
  text "X" at 12446.46,3867.6 h60
  text "TOP" at 12563.46,3867.6 h60
  text "X" at 12956.46,3867.6 h60
  text "BOTTOM" at 13074.46,3867.6 h60
  text "SILKSCREEN COLOR:" at 11488.68,3712.41 h60
  text "X" at 12445.46,3712.41 h60
  text "WHITE" at 12563.46,3712.41 h60
  text "OTHER" at 13074.46,3712.41 h60
  text "X" at 12576.46,3568.96 h60
  text "GREEN" at 12694.46,3568.96 h60
  text "OTHER" at 13312.46,3568.96 h60
  text "SOLDER RESIST COLOR:" at 11488.68,3562.1 h60
  text "X" at 12576.46,3414.71 h60
  text "MATTE" at 12694.46,3414.71 h60
  text "SEMI-GLOSS" at 13312,3414.07 h60
  text "IMMERSION GOLD (ENIG)" at 12394.46,3241.94 h60
  text "ENEPIG" at 13732,3234.72 h60
  text "SURFACE FINISH:" at 11333.46,3233.72 h60
  text "X" at 12216.46,3233.72 h60
  text "IMM. TIN/SILVER OR EQUIV" at 11663,3096.4 h60
  text "OTHER" at 13094.46,3092.47 h60
  text "ARRAY/PANEL:" at 11333.46,2937.09 h60
  text "CUT AND TRIM PER M1 BOARD OUTLINE" at 12394.46,2928.87 h60
  text "N.C. ROUTE" at 12394.46,2792.9 h60
  text "X" at 13082.46,2792.9 h60
  text "V. SCORE" at 13260.46,2792.9 h60
  text "CERTIFICATION:" at 11333.46,2663.77 h60
  text "MATERIALS AND WORKMANSHIP FOR ALL PCBS" at 12058.46,2663.77 h60
  text "TO MEET OR EXCEED THE REQUIREMENTS OF:" at 12058.46,2569.71 h60
  text "X" at 11695.97,2441.08 h60
  text "ANSI IPC-A-600F CLASS ->" at 11823.96,2441.08 h60
  text "X" at 13471.97,2441.08 h60
  text "2" at 13581.96,2441.08 h60
  text "1" at 13266.96,2439.58 h60
  text "3" at 13935.96,2439.58 h60
  text "X" at 12507.97,2293.39 h60
  text "RoHS" at 12635.96,2293.39 h60
  text "OTHER" at 13280.36,2293.39 h60
  text "PER ORDER" at 13677.42,2293.39 h60
  text "ALL BOARDS MUST MEET OR EXCEED UL94-V0 REQUIREMENTS." at 11361,2139.57 h60
  text "PCB MUST BEAR THE UL94V-0 UL REGISTERED MATERIAL ID NUMBER" at 11361,2023.5 h60
  text "ADDITIONAL REQUIREMENTS:" at 11333.46,1854.08 h60
  text "MICROSECTION:" at 11408.23,1746.95 h60
  text "YES" at 12313.96,1746.95 h60
  text "REQUIRED" at 13175.46,1602.62 h60
  text "BARE BOARD ELEC. TEST:" at 11408.23,1599.76 h60
  text "NONE" at 12713.96,1599.76 h60
  text "X" at 13057.46,1599.76 h60
  text "PER ORDER" at 13767.46,1599.76 h60
  text "XX MIL VIAS REQUIRE NON-CONDUCTIVE FILL AND PLANARIZE" at 11576.38,1394.82 h59
  text "XX MIL VIAS REQUIRE CONDUCTIVE FILL AND PLANARIZE" at 11584.38,1290.84 h60
  text "OUTER XX MIL TRACES REQUIRE 50 OHM SINGLE-ENDED IMPEDANCE" at 11583.39,1127.46 h58
  text "LAYER 2 & 3 (INNER LAYERS) XX MIL WIDE, XX MIL SPACE / TRACES REQUIRE 100 OHM DIFFERENTIAL IMPEDANCE" at 11575.39,891.74 h60
  text ".Layer_Name" at 577,-858.49 h60
M11 Gerber Information:
  lines w10: -292,-930.17 6308,-930.17 ; -292,-726.83 6310,-726.83 ; -292,-523.5 -292,-1133.5 3713,-1133.5 6310,-1133.5 6310,-523.5 -291.5,-523.5 -291.5,-1133.5 1284,-1133.5 ; 2173,-1133.5 2173,-523.5 ; 3440,-726.83 3440,-523.5 ; 4280,-726.83 4280,-523.5 ; 4902,-1140 4902,-937.17
  text "ALL ARTWORK VIEWED FROM TOP SIDE" at -228.5,-655.67 h60
  text "BOARD #:" at 2248,-655.67 h60
  text ".PRJ_Number" at 2793.5,-655.67 h60
  text "REV:" at 3638,-655.67 h60
  text ".PCB_Rev" at 3929.5,-655.67 h60
  text "SVN REV:" at 4476,-655.67 h60
  text ".VersionControl_RevNumber" at 4982,-655.67 h60
  text "LAYER NAME =" at -228.5,-858.49 h60
  text "TID #:" at 2248,-859 h60
  text ".TID" at 2793.5,-859 h60
  text "PLOT NAME =" at -228.5,-1064.34 h60
  text ".plot_File_Name" at 577,-1064.34 h60
  text "GENERATED    :" at 2250,-1064.34 h60
  text ".Print_Date" at 3119.5,-1064.34 h60
  text ".Print_Time" at 3848.5,-1064.34 h60
  text "TEXAS INSTRUMENTS" at 5113,-1064.34 h60
M12 Stackup:
  drawing of 295 lines, arcs and shapes, not listed
  text "Layer" at 9821.59,7874.94 h60
  text "Name" at 10231.51,7874.94 h60
  text "Material" at 11171.25,7874.94 h60
  text "Thickness" at 12031.02,7874.94 h60
  text "Constant" at 12680.85,7874.94 h60
  text "Board Layer Stack" at 13250.71,7874.94 h60
  text "Top Overlay" at 10231.51,7754.94 h60
  text "Top Solder" at 10231.51,7634.94 h60
  text "Solder Resist" at 11171.25,7634.94 h60
  text "0.40mil" at 12031.02,7634.94 h60
  text "3.5" at 12680.85,7634.94 h60
  text "1" at 9821.59,7514.94 h60
  text "Top Layer" at 10231.51,7514.94 h60
  text "2.80mil" at 12031.02,7514.94 h60
  text "Dielectric 1" at 10231.51,7394.94 h60
  text "FR-4 High Tg" at 11171.25,7394.94 h60
  text "5.00mil" at 12031.02,7394.94 h60
  text "4.2" at 12680.85,7394.94 h60
  text "2" at 9821.59,7274.94 h60
  text "Signal Layer 1" at 10231.51,7274.94 h60
  text "1.40mil" at 12031.02,7274.94 h60
  text "Dielectric 2" at 10231.51,7154.94 h60
  text "FR-4 High Tg" at 11171.25,7154.94 h60
  text "21.60mil" at 12031.02,7154.94 h60
  text "4.2" at 12680.85,7154.94 h60
  text "3" at 9821.59,7034.94 h60
  text "Signal Layer 2" at 10231.51,7034.94 h60
  text "1.40mil" at 12031.02,7034.94 h60
  text "Dielectric 3" at 10231.51,6914.94 h60
  text "FR-4 High Tg" at 11171.25,6914.94 h60
  text "5.00mil" at 12031.02,6914.94 h60
  text "4.2" at 12680.85,6914.94 h60
  text "4" at 9821.59,6794.94 h60
  text "Bottom Layer" at 10231.51,6794.94 h60
  text "2.80mil" at 12031.02,6794.94 h60
  text "Bottom Solder" at 10231.51,6674.94 h60
  text "Solder Resist" at 11171.25,6674.94 h60
  text "0.40mil" at 12031.02,6674.94 h60
  text "3.5" at 12680.85,6674.94 h60
  text "Bottom Overlay" at 10231.51,6554.94 h60
  text ".Layer_Name" at 577,-858.49 h60
M13 Component Bodies Top:
  text ".Layer_Name" at 577,-858.49 h60
M14 Component Bodies Bottom:
  text ".Layer_Name" at 577,-858.49 h60
M15 Courtyards Top:
  text ".Layer_Name" at 577,-858.49 h60
M16 Courtyards Bottom:
  text ".Layer_Name" at 577,-858.49 h60
Drill Drawing:
  circle w10: c5363.72,2668.68 r27.63
  circle w10: c5363.72,2047.08 r16.58
  circle w10: c5363.72,2047.08 r27.63
  lines w10: 5336.09,2143.78 5391.34,2143.78 5391.34,2199.03 5336.09,2199.03 5336.09,2143.78 ; 5336.09,2295.72 5363.72,2268.1 5391.34,2295.72 5363.72,2323.35 5336.09,2295.72 ; 5336.09,2392.42 5363.72,2406.23 5391.34,2392.42 5377.53,2420.04 5391.34,2447.67 5363.72,2433.86 5336.09,2447.67 5349.9,2420.04 5336.09,2392.42 ; 5336.09,2530.55 5349.9,2530.55 5363.72,2516.74 5377.53,2530.55 5391.34,2530.55 5377.53,2544.36 5391.34,2558.18 5377.53,2558.18 5363.72,2571.99 5349.9,2558.18 5336.09,2558.18 5349.9,2544.36 5336.09,2530.55 ; 5336.09,2820.63 5391.34,2820.63 5363.72,2765.38 5336.09,2820.63 ; 5336.09,2889.7 5391.34,2889.7 5391.34,2944.95 5336.09,2944.95 5336.09,2889.7 ; 5336.09,3027.83 5349.9,3027.83 5363.72,3014.02 5377.53,3027.83 5391.34,3027.83 5377.53,3041.64 5391.34,3055.46 5377.53,3055.46 5363.72,3069.27 5349.9,3055.46 5336.09,3055.46 5349.9,3041.64 5336.09,3027.83 ; 5336.09,3193.59 5391.34,3193.59 5363.72,3138.34 5336.09,3193.59 ; 5336.09,3262.66 5336.09,3276.47 5349.9,3290.28 5336.09,3304.1 5336.09,3317.91 5349.9,3317.91 5363.72,3304.1 5377.53,3317.91 5391.34,3317.91 5391.34,3304.1 5377.53,3290.28 5391.34,3276.47 5391.34,3262.66 5377.53,3262.66 5363.72,3276.47 5349.9,3262.66 5336.09,3262.66 ; 5347.14,2154.83 5380.29,2154.83 5380.29,2187.98 5347.14,2187.98 5347.14,2154.83 ; 5347.14,3033.35 5355.43,3033.35 5363.72,3025.07 5372.01,3033.35 5380.29,3033.35 5372.01,3041.64 5380.29,3049.93 5372.01,3049.93 5363.72,3058.22 5355.43,3049.93 5347.14,3049.93 5355.43,3041.64 5347.14,3033.35 ; 5347.14,3182.54 5380.29,3182.54 5363.72,3149.39 5347.14,3182.54
  lines w12: 5286,1982.16 8517.49,1982.16 ; 5286,3349.68 8517.49,3349.68 ; 5623.86,1857.84 5623.86,3474 ; 5955.86,1857.84 5955.86,3474 ; 6592.43,1857.84 6592.43,3474 ; 6851.57,1857.84 6851.57,3474 ; 7226.72,1857.84 7226.72,3474 ; 7951.05,1857.84 7951.05,3474 ; 5286,1857.84 8517.49,1857.84 8517.49,3474 5286,3474 5286,1857.84
  text "Symbol" at 5360.59,3386.98 h72
  text "Quantity" at 5661.16,3386.98 h72
  text "Finished Hole Size" at 5993.16,3386.98 h72
  text "Plated" at 6629.72,3386.98 h72
  text "Hole Type" at 6888.86,3386.98 h72
  text "Drill Layer Pair" at 7264.02,3386.98 h72
  text "Hole Tolerance" at 7988.35,3386.98 h72
  text "16" at 5661.16,3262.66 h60
  text "7.87mil (0.200mm)" at 5993.16,3262.66 h60
  text "PTH" at 6629.72,3262.66 h60
  text "Round" at 6888.86,3262.66 h60
  text "Top Layer - Bottom Layer" at 7264.02,3262.66 h60
  text "77" at 5661.16,3138.34 h60
  text "8.00mil (0.203mm)" at 5993.16,3138.34 h60
  text "PTH" at 6629.72,3138.34 h60
  text "Round" at 6888.86,3138.34 h60
  text "Top Layer - Bottom Layer" at 7264.02,3138.34 h60
  text "10" at 5661.16,3014.02 h60
  text "11.81mil (0.300mm)" at 5993.16,3014.02 h60
  text "PTH" at 6629.72,3014.02 h60
  text "Round" at 6888.86,3014.02 h60
  text "Top Layer - Bottom Layer" at 7264.02,3014.02 h60
  text "12" at 5661.16,2889.7 h60
  text "40.00mil (1.016mm)" at 5993.16,2889.7 h60
  text "PTH" at 6629.72,2889.7 h60
  text "Round" at 6888.86,2889.7 h60
  text "Top Layer - Bottom Layer" at 7264.02,2889.7 h60
  text "16" at 5661.16,2765.38 h60
  text "45.28mil (1.150mm)" at 5993.16,2765.38 h60
  text "PTH" at 6629.72,2765.38 h60
  text "Round" at 6888.86,2765.38 h60
  text "Top Layer - Bottom Layer" at 7264.02,2765.38 h60
  text "24" at 5661.16,2641.06 h60
  text "59.06mil (1.500mm)" at 5993.16,2641.06 h60
  text "PTH" at 6629.72,2641.06 h60
  text "Round" at 6888.86,2641.06 h60
  text "Top Layer - Bottom Layer" at 7264.02,2641.06 h60
  text "36" at 5661.16,2516.74 h60
  text "62.99mil (1.600mm)" at 5993.16,2516.74 h60
  text "PTH" at 6629.72,2516.74 h60
  text "Round" at 6888.86,2516.74 h60
  text "Top Layer - Bottom Layer" at 7264.02,2516.74 h60
  text "16" at 5661.16,2392.42 h60
  text "63.00mil (1.600mm)" at 5993.16,2392.42 h60
  text "PTH" at 6629.72,2392.42 h60
  text "Round" at 6888.86,2392.42 h60
  text "Top Layer - Bottom Layer" at 7264.02,2392.42 h60
  text "18" at 5661.16,2268.1 h60
  text "39.37mil (1.000mm)" at 5993.16,2268.1 h60
  text "NPTH" at 6629.72,2268.1 h60
  text "Slot" at 6888.86,2268.1 h60
  text "Top Layer - Bottom Layer" at 7264.02,2268.1 h60
  text "6" at 5661.16,2143.78 h60
  text "39.37mil (1.000mm)" at 5993.16,2143.78 h60
  text "NPTH" at 6629.72,2143.78 h60
  text "Slot" at 6888.86,2143.78 h60
  text "Top Layer - Bottom Layer" at 7264.02,2143.78 h60
  text "3" at 5661.16,2019.46 h60
  text "39.37mil (1.000mm)" at 5993.16,2019.46 h60
  text "NPTH" at 6629.72,2019.46 h60
  text "Slot" at 6888.86,2019.46 h60
  text "Top Layer - Bottom Layer" at 7264.02,2019.46 h60
  text "234 Total" at 5661.16,1895.14 h60
  text "Slot definitions :" at 5360.59,1808.11 h60
  text "Routed Path Length" at 5811.31,1808.11 h60
  text "= Calculated from tool start centre position to tool end centre position." at 6351.05,1808.11 h60
  text "Hole Length" at 5811.31,1758.38 h60
  text "= Routed Path Length + Tool Size = Slot length as defined in the PCB layout" at 6151.24,1758.38 h60
  text ".Layer_Name" at 577,-858.49 h60
M17 Embedded Cavity:
  text ".Layer_Name" at 577,-858.49 h60
M18 Embedded Assembly:
  text ".Layer_Name" at 577,-858.49 h60
M19 Embedded Keepout:
  text ".Layer_Name" at 577,-858.49 h60

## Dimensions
0,-400 to 1000,-400 on M2 Board Dimensions
0,0 to 0,7480.32 on M2 Board Dimensions
0,0 to 3543.31,0 on M2 Board Dimensions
